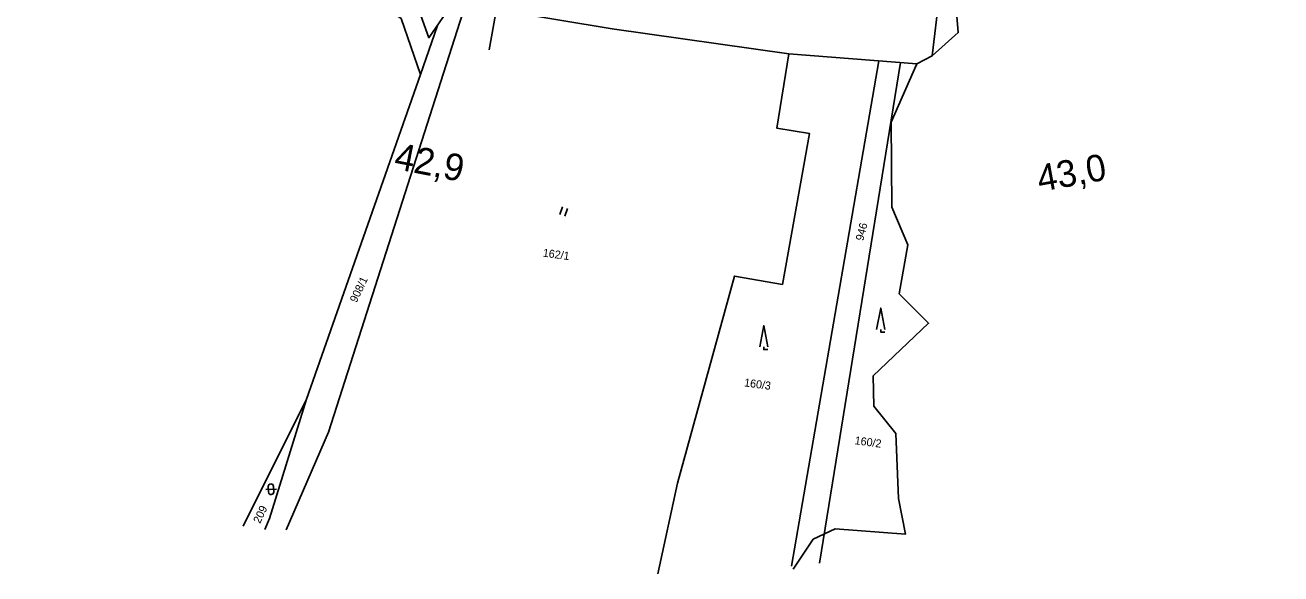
# Model space of a CAD drawing. Extents: x -514509 to -512782, y -1144610 to -1143439.
# Drawn here: x -513017.7 to -512782.3, y -1143771 to -1143668.1 of the extents above; entities that cross this region are included whole.
import ezdxf

# ---------------------------------------------------------------- set-up
doc = ezdxf.new("R2010")
doc.units = 0
for name, color, linetype in [('Vrstva 10', 7, 'Continuous'), ('Vrstva 15', 7, 'Continuous'), ('Vrstva 39', 7, 'Continuous'), ('Vrstva 7', 7, 'Continuous'), ('Vrstva 8', 7, 'Continuous'), ('Vrstva 9', 7, 'Continuous')]:
    doc.layers.add(name, color=color, linetype=linetype)

msp = doc.modelspace()

# ---------------------------------------------------------------- linework, layer by layer
at = {"layer": 'Vrstva 10'}
msp.add_lwpolyline([(-512782.341, -1143656.666), (-512796.89, -1143661.893), (-512815.309, -1143658.506), (-512846.358, -1143662.813), (-512847.692, -1143673.887), (-512850.552, -1143675.414), (-512874.542, -1143673.507), (-512907.663, -1143668.822), (-512937.442, -1143663.927), (-512942.033, -1143670.511), (-512944.784, -1143662.787), (-512958.978, -1143654.892), (-512977.284, -1143642.016), (-512997.25, -1143628.575), (-513034.474, -1143613.524), (-513050.89, -1143616.331), (-513050.251, -1143607.386), (-513065.331, -1143600.696), (-513084.436, -1143602.206), (-513086.215, -1143618.123), (-513093.877, -1143618.167), (-513107.772, -1143623.787)], dxfattribs=at)
msp.add_lwpolyline([(-512782.341, -1143656.666), (-512796.89, -1143661.893), (-512815.309, -1143658.506), (-512846.358, -1143662.813), (-512847.692, -1143673.887), (-512850.552, -1143675.414), (-512874.542, -1143673.507), (-512907.663, -1143668.822), (-512937.442, -1143663.927), (-512942.033, -1143670.511), (-512944.784, -1143662.787), (-512958.978, -1143654.892), (-512977.284, -1143642.016), (-512997.25, -1143628.575), (-513034.474, -1143613.524), (-513050.89, -1143616.331), (-513050.251, -1143607.386), (-513065.331, -1143600.696), (-513084.436, -1143602.206), (-513086.215, -1143618.123), (-513093.877, -1143618.167), (-513107.772, -1143623.787)], dxfattribs=at)
at = {"layer": 'Vrstva 39'}
msp.add_lwpolyline([(-512923.69, -1143633.414), (-512924.244, -1143636.5), (-512930.755, -1143672.785)], dxfattribs=at)
at = {"layer": 'Vrstva 8'}
for p, q in [((-512874.035, -1143769.508), (-512857.725, -1143674.843)), ((-512853.628, -1143675.169), (-512868.803, -1143768.981)), ((-512976.817, -1143762.03), (-512964.949, -1143738.205))]:
    msp.add_line(p, q, dxfattribs=at)
for points in [[(-512817.217, -1143602.565), (-512829.577, -1143605.491), (-512829.119, -1143611.736), (-512826.292, -1143620.784), (-512828.281, -1143628.402), (-512816.231, -1143640.787), (-512816.096, -1143647.518), (-512824.494, -1143650.991), (-512837.936, -1143643.501), (-512842.862, -1143645.807), (-512840.537, -1143656.803), (-512843.361, -1143662.667), (-512842.806, -1143669.533), (-512847.692, -1143673.887), (-512850.552, -1143675.414), (-512850.702, -1143675.751)], [(-512943.619, -1143677.37), (-512947.237, -1143666.922), (-512998.363, -1143631.864), (-513032.73, -1143619.331), (-513048.971, -1143618.929), (-513060.702, -1143623.149), (-513088.843, -1143624.07), (-513104.89, -1143628.486)], [(-512968.754, -1143762.704), (-512960.812, -1143744.44), (-512935.187, -1143664.296)], [(-512940.431, -1143668.214), (-512943.619, -1143677.37), (-512964.949, -1143738.205), (-512971.91, -1143760.593), (-512972.779, -1143762.673)], [(-512874.542, -1143673.507), (-512876.809, -1143687.476), (-512870.71, -1143688.445), (-512875.768, -1143716.723), (-512884.772, -1143715.155), (-512895.417, -1143753.946), (-512899.089, -1143770.961)], [(-512873.753, -1143770.064), (-512870.001, -1143764.482), (-512865.905, -1143762.516), (-512852.715, -1143763.523), (-512853.994, -1143756.834), (-512854.508, -1143744.653), (-512858.61, -1143739.555), (-512858.786, -1143733.867), (-512848.374, -1143724), (-512853.912, -1143718.474), (-512852.261, -1143709.335), (-512855.246, -1143702.274), (-512855.381, -1143686.3), (-512850.552, -1143675.414)]]:
    msp.add_lwpolyline(points, dxfattribs=at)
at = {"layer": 'Vrstva 9'}
for p, q in [((-512916.992, -1143702.194), (-512917.476, -1143703.614)), ((-512916.531, -1143703.937), (-512916.044, -1143702.518)), ((-512972.612, -1143755.139), (-512970.613, -1143755.064)), ((-512972.132, -1143754.618), (-512972.095, -1143755.618)), ((-512971.132, -1143754.582), (-512971.096, -1143755.582))]:
    msp.add_line(p, q, dxfattribs=at)
for points in [[(-512858.1, -1143725.157), (-512857.35, -1143721.157), (-512856.6, -1143725.157)], [(-512880.019, -1143728.445), (-512879.269, -1143724.445), (-512878.519, -1143728.445)], [(-512857.35, -1143725.157), (-512857.35, -1143725.657), (-512856.6, -1143725.657)], [(-512879.269, -1143728.445), (-512879.269, -1143728.945), (-512878.519, -1143728.945)]]:
    msp.add_lwpolyline(points, dxfattribs=at)
for centre, start, end in [((-512971.632, -1143754.601), 2.05659, 182.05659), ((-512971.596, -1143755.6), 182.05659, 2.05659)]:
    msp.add_arc(centre, 0.5, start, end, dxfattribs=at)

# ---------------------------------------------------------------- texts
at = {"layer": 'Vrstva 15'}
msp.add_text('43,0', height=5, rotation=10.291, dxfattribs=at).set_placement((-512827.557, -1143699.398))
at = {"layer": 'Vrstva 7'}
msp.add_text('42,9', height=5, rotation=348.89938, dxfattribs=at).set_placement((-512948.745, -1143695.026))
at = {"layer": 'Vrstva 9'}
for s, rotation, p in [('946', 75.79212, (-512860.614, -1143708.653)), ('162/1', 352.22933, (-512920.741, -1143711.501)), ('908/1', 64.48719, (-512955.576, -1143720.255)), ('160/3', 352.22933, (-512883.006, -1143735.816)), ('160/2', 352.22933, (-512862.288, -1143746.655)), ('209', 64.48719, (-512973.678, -1143761.647))]:
    msp.add_text(s, height=1.5, rotation=rotation, dxfattribs=at).set_placement(p)

doc.saveas('drawing.dxf')
